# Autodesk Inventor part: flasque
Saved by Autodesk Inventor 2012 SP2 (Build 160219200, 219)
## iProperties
Created: 2013-04
Part Number: flasque
Material: Default
Document SubType Name: Modeling
Designer: papa
Density: 1 g/cm^3
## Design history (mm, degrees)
node "flasque1"
node "flasque"
node "Base1"
